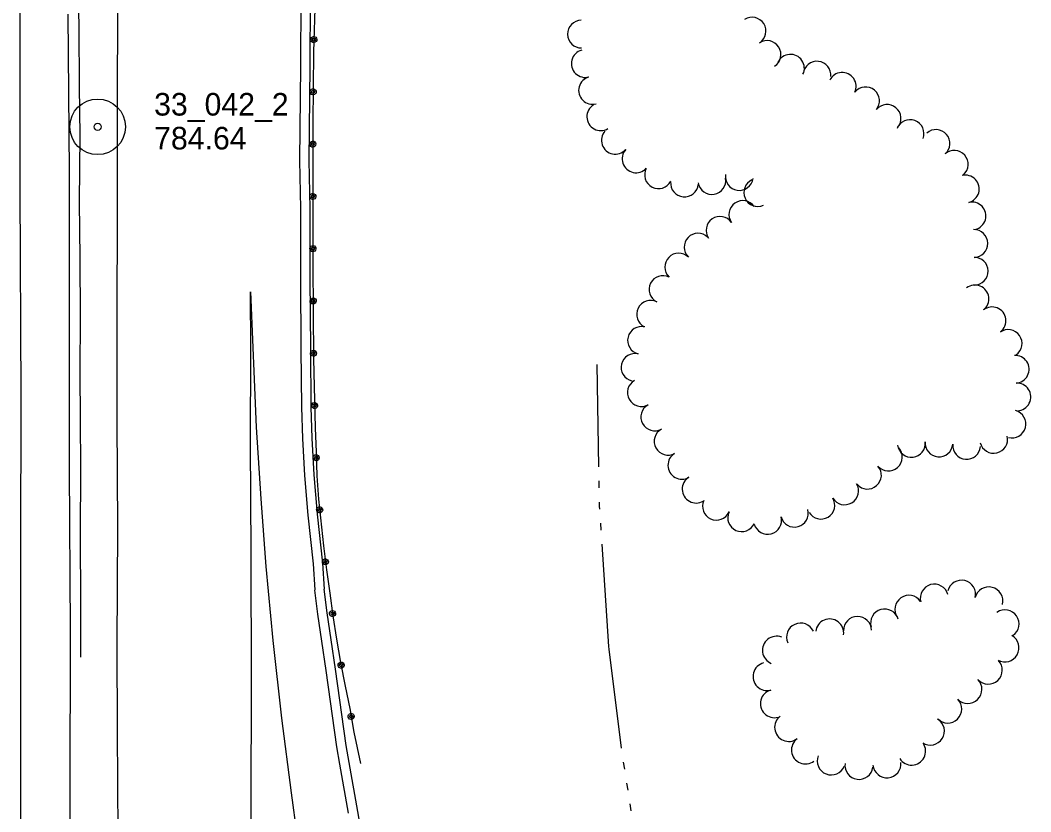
# Model space of a CAD drawing. Extents: x 589250 to 1188077, y 162953 to 363065.
# Drawn here: x 594036.3 to 594304.5, y 174529.2 to 174739.4 of the extents above; entities that cross this region are included whole.
import ezdxf

# ---------------------------------------------------------------- set-up
doc = ezdxf.new("R2010")
doc.units = 0
for name, color, linetype in [('E_BMGRD_P', 7, 'Continuous'), ('E_DRN_Pipe', 7, 'Continuous'), ('E_LAND_TreeLine_P', 7, 'Continuous'), ('E_MAP_PassPoints', 7, 'Continuous'), ('E_RDWY', 7, 'Continuous'), ('E_RDWY_C_and_G', 7, 'Continuous'), ('E_WAL', 7, 'Continuous'), ('E_WTR_FlowLine', 7, 'Continuous')]:
    doc.layers.add(name, color=color, linetype=linetype)

msp = doc.modelspace()

# ---------------------------------------------------------------- linework, layer by layer
at = {"layer": 'E_BMGRD_P'}
for p, q in [((594114.66, 174749.28), (594114.09, 174730.88)), ((594114.09, 174730.88), (594113.9, 174712.12)), ((594113.9, 174712.12), (594113.93, 174693.36)), ((594113.93, 174693.36), (594113.97, 174674.6)), ((594113.97, 174674.6), (594114.11, 174649.46)), ((594114.11, 174649.46), (594114.51, 174631.15)), ((594114.51, 174631.15), (594114.77, 174624.7)), ((594114.77, 174624.7), (594114.96, 174618.4)), ((594114.96, 174618.4), (594115.43, 174612.26)), ((594115.43, 174612.26), (594116.77, 174599.82)), ((594116.77, 174599.82), (594117.54, 174593.46)), ((594117.54, 174593.46), (594118.4, 174587.24)), ((594118.4, 174587.24), (594119.24, 174581.25)), ((594119.24, 174581.25), (594120.24, 174575.04)), ((594120.24, 174575.04), (594121.31, 174568.83)), ((594121.31, 174568.83), (594122.54, 174562.62)), ((594122.54, 174562.62), (594123.75, 174556.64)), ((594123.75, 174556.64), (594124.83, 174550.35)), ((594124.83, 174550.35), (594126.6, 174542.08))]:
    msp.add_line(p, q, dxfattribs=at)
for centre, major_axis, ratio in [((594114.19, 174734.26), (0.541, 0.601), 0.999389), ((594114.19, 174734.26), (0.272, 0.303), 0.999389), ((594113.98, 174720.38), (0.465, 0.661), 0.99949), ((594113.98, 174720.38), (0.234, 0.333), 0.99949), ((594113.91, 174706.5), (0.54, 0.602), 0.999384), ((594113.91, 174706.5), (0.272, 0.303), 0.999384), ((594113.94, 174692.62), (0.383, 0.712), 0.999561), ((594113.94, 174692.62), (0.193, 0.359), 0.999561), ((594113.96, 174678.74), (0.383, 0.712), 0.999561), ((594113.96, 174678.74), (0.193, 0.359), 0.999561), ((594114.02, 174664.86), (0.335, 0.736), 0.99959), ((594114.02, 174664.86), (0.169, 0.371), 0.99959), ((594114.1, 174650.98), (0.335, 0.736), 0.99959), ((594114.1, 174650.98), (0.169, 0.371), 0.99959), ((594114.38, 174637.1), (0.471, 0.657), 0.999485), ((594114.38, 174637.1), (0.237, 0.331), 0.999485), ((594114.81, 174623.23), (0.56, 0.583), 0.999337), ((594114.81, 174623.23), (0.282, 0.294), 0.999337), ((594115.74, 174609.39), (0.417, 0.693), 0.99955), ((594115.74, 174609.39), (0.21, 0.349), 0.99955), ((594117.28, 174595.6), (0.583, 0.56), 0.999228), ((594117.28, 174595.6), (0.294, 0.282), 0.999228), ((594119.16, 174581.85), (0.51, 0.627), 0.99942), ((594119.16, 174581.85), (0.257, 0.316), 0.99942), ((594121.45, 174568.16), (0.505, 0.632), 0.999426), ((594121.45, 174568.16), (0.254, 0.318), 0.999426), ((594124.11, 174554.55), (0.654, 0.476), 0.998716), ((594124.11, 174554.55), (0.329, 0.24), 0.998716)]:
    msp.add_ellipse(centre, major_axis=major_axis, ratio=ratio, dxfattribs=at)
at = {"layer": 'E_DRN_Pipe'}
msp.add_lwpolyline([(594051.55, 174751.58), (594051.8, 174737.38), (594051.92, 174721.82), (594052.11, 174708.83), (594051.93, 174691.21), (594052.07, 174676.18), (594052.18, 174660.74), (594052.08, 174645.84), (594052.14, 174633.38), (594052.26, 174620.42), (594052.22, 174602.46), (594052.29, 174584.68), (594052.27, 174570.24)], dxfattribs=at)
at = {"layer": 'E_LAND_TreeLine_P'}
for centre, radius, start, end in [((594185.21, 174735.72), 3.68, 91.0072, 271.0072), ((594230.51, 174736.5), 3.68, 302.6147, 122.6147), ((594234.48, 174730.29), 3.68, 302.6147, 122.6147), ((594186.24, 174727.88), 3.68, 105.0434, 285.0434), ((594240.7, 174726.64), 3.68, 334.4421, 154.4421), ((594247.74, 174724.82), 3.68, 353.8822, 173.8822), ((594254.44, 174721.85), 3.68, 334.4421, 154.4421), ((594188.15, 174720.76), 3.68, 105.0434, 285.0434), ((594260.66, 174717.99), 3.68, 320.6426, 140.6426), ((594190.35, 174713.77), 3.68, 121.2636, 301.2636), ((594266.36, 174713.32), 3.68, 320.6426, 140.6426), ((594272.43, 174709.3), 3.68, 339.2058, 159.2058), ((594194.21, 174707.5), 3.68, 138.1283, 318.1283), ((594279.32, 174706.67), 3.68, 311.2435, 131.2435), ((594199.7, 174702.58), 3.68, 138.1283, 318.1283), ((594284.17, 174701.13), 3.68, 311.2435, 131.2435), ((594205.67, 174698.36), 3.68, 152.3967, 332.3967), ((594227.12, 174697.9), 3.68, 171.5449, 351.5449), ((594287.12, 174694.59), 3.68, 283.8114, 103.8114), ((594212.56, 174696.16), 3.68, 174.667, 354.667), ((594219.85, 174696.83), 3.68, 189.5379, 9.5379), ((594231.99, 174693.62), 3.68, 114.2058, 294.2058), ((594228.06, 174687.81), 3.68, 34.6972, 214.6972), ((594288.88, 174687.44), 3.68, 283.8114, 103.8114), ((594222, 174683.61), 3.68, 34.6972, 214.6972), ((594216.16, 174679.16), 3.68, 46.0072, 226.0072), ((594289.36, 174680.12), 3.68, 271.0072, 91.0072), ((594211.04, 174673.86), 3.68, 46.0072, 226.0072), ((594289.49, 174672.75), 3.68, 271.0072, 91.0072), ((594206.85, 174667.9), 3.68, 63.3612, 243.3612), ((594289.68, 174665.4), 3.68, 307.8771, 127.8771), ((594203.55, 174661.31), 3.68, 63.3612, 243.3612), ((594294.21, 174659.59), 3.68, 307.8771, 127.8771), ((594201.16, 174654.39), 3.68, 76.3863, 256.3863), ((594298.47, 174653.58), 3.68, 304.6972, 124.6972), ((594199.42, 174647.23), 3.68, 76.3863, 256.3863), ((594300.34, 174646.72), 3.68, 273.4967, 93.4967), ((594201.1, 174640.52), 3.68, 118.8313, 298.8313), ((594300.79, 174639.36), 3.68, 273.4967, 93.4967), ((594204.66, 174634.07), 3.68, 118.8313, 298.8313), ((594299.49, 174632.18), 3.68, 255.0618, 75.0618), ((594208.21, 174627.61), 3.68, 118.8313, 298.8313), ((594294.64, 174628.09), 3.68, 193.536, 13.536), ((594266.69, 174623.43), 3.68, 221.1081, 41.1081), ((594272.8, 174627.03), 3.68, 186.7178, 6.7178), ((594280.12, 174627.15), 3.68, 174.9982, 354.9982), ((594287.47, 174626.5), 3.68, 174.9982, 354.9982), ((594211.85, 174621.21), 3.68, 121.0758, 301.0758), ((594261.14, 174618.59), 3.68, 221.1081, 41.1081), ((594215.65, 174614.89), 3.68, 121.0758, 301.0758), ((594255.08, 174614.43), 3.68, 211.0758, 31.0758), ((594221.04, 174610.36), 3.68, 155.4472, 335.4472), ((594248.77, 174610.63), 3.68, 211.0758, 31.0758), ((594241.75, 174608.49), 3.68, 195.0434, 15.0434), ((594227.74, 174607.3), 3.68, 155.4472, 335.4472), ((594234.64, 174606.58), 3.68, 195.0434, 15.0434), ((594286.09, 174586.99), 3.73, 346.0758, 166.0758), ((594278.87, 174585.93), 3.73, 15.0434, 195.0434), ((594293.34, 174585.2), 3.73, 346.0758, 166.0758), ((594272.13, 174582.97), 3.73, 34.6972, 214.6972), ((594265.69, 174579.34), 3.73, 15.9386, 195.9386), ((594297.63, 174579.11), 3.73, 304.6972, 124.6972), ((594251.09, 174576.7), 3.73, 352.8771, 172.8771), ((594258.5, 174577.36), 3.73, 1.0072, 181.0072), ((594243.39, 174575.6), 3.73, 24.6366, 204.6366), ((594236.99, 174572.11), 3.73, 68.3873, 248.3873), ((594297.61, 174572.76), 3.73, 240.7507, 60.7507), ((594293.19, 174566.85), 3.73, 222.9944, 42.9944), ((594234.49, 174565.15), 3.73, 105.0434, 285.0434), ((594287.77, 174561.72), 3.73, 224.1596, 44.1596), ((594236.43, 174557.94), 3.73, 105.0434, 285.0434), ((594282.41, 174556.52), 3.73, 224.1596, 44.1596), ((594240.23, 174551.63), 3.73, 126.8448, 306.8448), ((594277.82, 174550.68), 3.73, 237.3171, 57.3171), ((594244.7, 174545.65), 3.73, 126.8448, 306.8448), ((594272.83, 174545.35), 3.73, 212.6147, 32.6147), ((594251.52, 174542.73), 3.73, 158.3873, 338.3873), ((594266.31, 174541.99), 3.73, 185.4059, 5.4059), ((594258.88, 174541.55), 3.73, 172.261, 352.261)]:
    msp.add_arc(centre, radius, start, end, dxfattribs=at)
at = {"layer": 'E_MAP_PassPoints'}
for radius in [7.38, 0.945]:
    msp.add_circle((594056.81, 174711.1), radius, dxfattribs=at)
at = {"layer": 'E_RDWY'}
for p, q in [((594036.28, 174694.37), (594036.26, 174752.99)), ((594062.09, 174716.87), (594062.14, 174743.69)), ((594062.07, 174688.5), (594062.09, 174716.87)), ((594036.48, 174639.81), (594036.28, 174694.37)), ((594062.04, 174660.46), (594062.07, 174688.5)), ((594097.39, 174667.31), (594098.89, 174631.35)), ((594097.49, 174652.09), (594097.39, 174667.31)), ((594062.01, 174632.95), (594062.04, 174660.46)), ((594097.41, 174626.82), (594097.49, 174652.09)), ((594036.45, 174598.19), (594036.48, 174639.81)), ((594062.16, 174604.75), (594062.01, 174632.95)), ((594098.89, 174631.35), (594100.09, 174612.34)), ((594097.57, 174598.28), (594097.41, 174626.82)), ((594100.09, 174612.34), (594101.44, 174594.37)), ((594062.02, 174573.43), (594062.16, 174604.75)), ((594036.4, 174529.41), (594036.45, 174598.19)), ((594097.66, 174563.33), (594097.57, 174598.28)), ((594101.44, 174594.37), (594103.35, 174574.67)), ((594103.35, 174574.67), (594105.61, 174554.12)), ((594062.07, 174550.76), (594062.02, 174573.43)), ((594097.54, 174530.97), (594097.66, 174563.33)), ((594105.61, 174554.12), (594108.21, 174534.27)), ((594062.35, 174502.22), (594062.07, 174550.76)), ((594108.21, 174534.27), (594111, 174513.38)), ((594036.48, 174482.06), (594036.4, 174529.41)), ((594097.78, 174493.36), (594097.54, 174530.97))]:
    msp.add_line(p, q, dxfattribs=at)
at = {"layer": 'E_RDWY_C_and_G'}
for p, q in [((594110.77, 174759.9), (594110.66, 174727.18)), ((594113.27, 174759.9), (594113.16, 174727.16)), ((594110.66, 174727.18), (594110.41, 174702.12)), ((594113.16, 174727.16), (594112.91, 174702.13)), ((594110.41, 174702.12), (594110.63, 174689.43)), ((594112.91, 174702.13), (594113.13, 174689.45)), ((594110.63, 174689.43), (594110.62, 174670.93)), ((594113.13, 174689.45), (594113.12, 174670.94)), ((594110.62, 174670.93), (594110.78, 174652.08)), ((594113.12, 174670.94), (594113.28, 174652.09)), ((594110.78, 174652.08), (594110.88, 174636.62)), ((594113.28, 174652.09), (594113.38, 174636.67)), ((594110.88, 174636.62), (594111.2, 174628.34)), ((594113.38, 174636.67), (594113.69, 174628.45)), ((594111.2, 174628.34), (594111.71, 174618.52)), ((594113.69, 174628.45), (594114.21, 174618.69)), ((594111.71, 174618.52), (594112.59, 174608.01)), ((594114.21, 174618.69), (594115.08, 174608.25)), ((594112.59, 174608.01), (594114.01, 174595.03)), ((594115.08, 174608.25), (594116.5, 174595.25)), ((594114.01, 174595.03), (594114.46, 174588.19)), ((594116.5, 174595.25), (594116.95, 174588.35)), ((594115.28, 174581.68), (594114.47, 174588.04)), ((594117.75, 174582.02), (594116.95, 174588.35)), ((594116.33, 174574.52), (594115.28, 174581.68)), ((594118.8, 174574.89), (594117.75, 174582.02)), ((594117.5, 174566.71), (594116.33, 174574.52)), ((594119.98, 174567.06), (594118.8, 174574.89)), ((594120.29, 174546.43), (594117.5, 174566.71)), ((594122.76, 174546.81), (594119.98, 174567.06)), ((594121.06, 174541.89), (594120.29, 174546.43)), ((594123.53, 174542.32), (594122.76, 174546.81)), ((594125.83, 174529.33), (594123.53, 174542.32)), ((594123.37, 174528.89), (594121.06, 174541.89)), ((594128.01, 174517.26), (594125.83, 174529.33))]:
    msp.add_line(p, q, dxfattribs=at)
at = {"layer": 'E_WAL'}
for p, q in [((594049.38, 174699.14), (594048.99, 174741.01)), ((594049.36, 174661.25), (594049.38, 174699.14)), ((594049.38, 174620.24), (594049.36, 174661.25)), ((594049.62, 174577.5), (594049.38, 174620.24)), ((594049.53, 174533.03), (594049.62, 174577.5)), ((594049.46, 174497.31), (594049.53, 174533.03))]:
    msp.add_line(p, q, dxfattribs=at)
at = {"layer": 'E_WTR_FlowLine'}
for p, q in [((594189.86, 174620.84), (594189.38, 174648.02)), ((594189.96, 174615.22), (594189.93, 174617.09)), ((594190.04, 174610.38), (594190.02, 174611.47)), ((594190.1, 174609.59), (594190.04, 174610.38)), ((594190.47, 174603.98), (594190.34, 174605.85)), ((594192.51, 174573.11), (594190.72, 174600.24)), ((594192.56, 174572.4), (594192.51, 174573.11)), ((594195.87, 174546.13), (594192.56, 174572.4)), ((594196.71, 174540.56), (594196.42, 174542.42)), ((594197.58, 174535), (594197.29, 174536.86)), ((594198.45, 174529.45), (594198.16, 174531.3))]:
    msp.add_line(p, q, dxfattribs=at)

# ---------------------------------------------------------------- texts
at = {"layer": 'E_MAP_PassPoints'}
for s, p in [('33_042_2', (594071.81, 174714.08)), ('784.64', (594071.81, 174705.08))]:
    msp.add_text(s, height=6, dxfattribs=at).set_placement(p)

doc.saveas('drawing.dxf')
